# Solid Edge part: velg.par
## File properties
Author: Romil
Template: iso part.par
Last saved by: Romil
Revision: 39
Application: Solid Edge
Material: Aluminum, 1060
Face Style: Aluminum
Fill Style: ANSI38(Aluminum)
Virtual Style: Polished aluminum
Coef. of Thermal Exp: 2.3e-05
Thermal Conductivity: 221.0
Specific Heat: 920.0
Modulus of Elasticity: 68947570000.0
Poisson's Ratio: 0.33
Yield Stress: 27579028.0
Ultimate Stress: 68947570.0
Elongation: 0.0
Density: 2712.000 kg/m^3
Accuracy: 0.990
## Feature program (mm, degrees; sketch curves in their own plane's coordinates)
sketch for "unnamed RevolvedProtrusion 1" plane through (0, 0, 0) normal (0, -1, 0) x-axis (1, 0, 0)
  line (7.5, 13.4) -> (-5.0414, 13.4)
  line (-6.2745, 13.4) -> (-5.0414, 13.4)
  arc centre (-6.2745, 13.5) radius 0.1 from (-6.2745, 13.4) to (-6.3506, 13.4351) cw
  line (-7.5761, 14.872) -> (-6.3506, 13.4351)
  arc centre (-7.5, 14.9369) radius 0.1 from (-7.6, 14.9369) to (-7.5761, 14.872) ccw
  line (-7.6, 18.3) -> (-7.6, 14.9369)
  arc centre (-7.7, 18.3) radius 0.1 from (-7.6, 18.3) to (-7.7, 18.4) ccw
  line (-7.7, 18.4) -> (-9.3, 18.4)
  arc centre (-9.3, 18.3) radius 0.1 from (-9.3, 18.4) to (-9.4, 18.3) ccw
  line (-9.4, 18.3) -> (-9.4, 15)
  arc centre (-9.5, 15) radius 0.1 from (-9.5, 14.9) to (-9.4, 15) ccw
  line (-9.5, 14.9) -> (-11.8, 14.9)
  arc centre (-11.8, 15) radius 0.1 from (-11.8, 14.9) to (-11.9, 15) cw
  line (-11.9, 15.8) -> (-11.9, 15)
  arc centre (-12, 15.8) radius 0.1 from (-12, 15.9) to (-11.9, 15.8) cw
  line (-12, 15.9) -> (-13, 15.9)
  arc centre (-13, 15.8) radius 0.1 from (-13, 15.9) to (-13.1, 15.8) ccw
  line (-13.1, 15.8) -> (-13.1, 14.2)
  line (-11.2018, 14.2) -> (-13.1, 14.2)
  line (-11.2018, 14.2) -> (-7.3, 11.9)
  line (-3.9, 11.9) -> (-7.3, 11.9)
  line (-3.9, 8) -> (-3.9, 11.9)
  line (-3.9, 8) -> (-3.9, 3.6)
  line (-3.9, 3.6) -> (-8.3, 3.6)
  line (-8.3, 3.6) -> (-8.3, 0)
  line (-8.3, 0) -> (0, 0)
  line (0, 0) -> (0, 3.9)
  line (0, 3.9) -> (3.9, 3.9)
  line (3.9, 8) -> (3.9, 3.9)
  line (4.6527, 8) -> (3.9, 8)
  arc centre (4.6527, 8.1) radius 0.1 from (4.6527, 8) to (4.73, 8.0366) ccw
  line (4.73, 8.0366) -> (7.9, 11.9)
  line (8.9, 11.9) -> (7.9, 11.9)
  line (13.1, 12.6985) -> (8.9, 11.9)
  line (13.1, 12.6985) -> (13.1, 13.4)
  line (13.1, 13.4) -> (13.1, 14.8)
  arc centre (13, 14.8) radius 0.1 from (13, 14.9) to (13.1, 14.8) cw
  line (13, 14.9) -> (12, 14.9)
  arc centre (12, 14.8) radius 0.1 from (12, 14.9) to (11.9, 14.8) ccw
  line (11.9, 13.5) -> (11.9, 14.8)
  arc centre (11.8, 13.5) radius 0.1 from (11.8, 13.4) to (11.9, 13.5) ccw
  line (11.8, 13.4) -> (9.5, 13.4)
  arc centre (9.5, 13.5) radius 0.1 from (9.4, 13.5) to (9.5, 13.4) ccw
  line (9.4, 13.5) -> (9.4, 18.3)
  arc centre (9.3, 18.3) radius 0.1 from (9.3, 18.4) to (9.4, 18.3) cw
  line (9.3, 18.4) -> (7.7, 18.4)
  arc centre (7.7, 18.3) radius 0.1 from (7.7, 18.4) to (7.6, 18.3) ccw
  line (7.6, 13.5) -> (7.6, 18.3)
  arc centre (7.5, 13.5) radius 0.1 from (7.5, 13.4) to (7.6, 13.5) ccw
revolve "unnamed RevolvedProtrusion 1" add finite 360 deg
sketch for "unnamed Cutout 1" plane through (0, 0, 0) normal (1, 0, 0) x-axis (0, 1, 0)
  arc centre (0, 0) radius 2.55 from (2.3238, 1.0501) to (0.15, 2.5456) ccw
  line (0.15, 2.5456) -> (0.15, 1.65)
  arc centre (0, 1.65) radius 0.15 from (0.15, 1.65) to (-0.15, 1.65) cw
  line (-0.15, 1.65) -> (-0.15, 2.5456)
  arc centre (0, 0) radius 2.55 from (-0.15, 2.5456) to (-2.3238, 1.0501) ccw
  line (-2.3238, 1.0501) -> (-1.9118, 0.6382)
  arc centre (-2.55, 0) radius 0.9025 from (-1.9118, 0.6382) to (-1.9118, -0.6382) cw
  line (-1.9118, -0.6382) -> (-2.3238, -1.0501)
  arc centre (0, 0) radius 2.55 from (-2.3238, -1.0501) to (-0.15, -2.5456) ccw
  line (-0.15, -2.5456) -> (-0.15, -1.65)
  arc centre (0, -1.65) radius 0.15 from (-0.15, -1.65) to (0.15, -1.65) cw
  line (0.15, -1.65) -> (0.15, -2.5456)
  arc centre (0, 0) radius 2.55 from (0.15, -2.5456) to (2.3238, -1.0501) ccw
  line (2.3238, -1.0501) -> (1.9118, -0.6382)
  arc centre (2.55, 0) radius 0.9025 from (1.9118, -0.6382) to (1.9118, 0.6382) cw
  line (1.9118, 0.6382) -> (2.3238, 1.0501)
extrude "unnamed Cutout 1" cut finite 1471.9732 symmetric
sketch for "ExtrudedCutout_21" plane through (0, 0, 0) normal (1, 0, 0) x-axis (0, 1, 0)
  circle centre (8, 0) radius 2.4
extrude "ExtrudedCutout_21" cut finite 1031.1369 symmetric
sketch for "unnamed Cutout 2" plane through (13.1, 0, 0) normal (1, 0, 0) x-axis (0, 1, 0)
  circle centre (8, 0) radius 3.9
extrude "unnamed Cutout 2" cut to key point along -normal
sketch for "ExtrudedCutout_25" plane through (3.9, 1.95, 0) normal (1, 0, 0) x-axis (0, 1, 0)
  circle centre (6.05, 0) radius 3.1
extrude "ExtrudedCutout_25" cut finite 0.9 along -normal
pattern "unnamed Pattern 1" of "ExtrudedCutout_25", "unnamed Cutout 2", "ExtrudedCutout_21"
extrude "unnamed Cutout 3" cut finite 1031.1369 symmetric
extrude "unnamed Cutout 4" cut finite 9.2
extrude "unnamed Cutout 5" cut finite 0.9
extrude "unnamed Cutout 6" cut finite 1031.1369 symmetric
extrude "unnamed Cutout 7" cut finite 9.2
extrude "unnamed Cutout 8" cut finite 0.9
extrude "unnamed Cutout 9" cut finite 1031.1369 symmetric
extrude "unnamed Cutout 10" cut finite 9.2
extrude "unnamed Cutout 11" cut finite 0.9
extrude "unnamed Cutout 12" cut finite 1031.1369 symmetric
extrude "unnamed Cutout 13" cut finite 9.2
extrude "unnamed Cutout 14" cut finite 0.9
extrude "unnamed Cutout 15" cut finite 1031.1369 symmetric
extrude "unnamed Cutout 16" cut finite 9.2
extrude "unnamed Cutout 17" cut finite 0.9
sketch for "ExtrudedCutout_41" plane through (-3.9, 0, 0) normal (-1, 0, 0) x-axis (0, 0, -1)
  circle centre (0, -8) radius 3.1
extrude "ExtrudedCutout_41" cut finite 0.9 along -normal
pattern "unnamed Pattern 2" of "ExtrudedCutout_41"
extrude "unnamed Cutout 18" cut finite 0.9
extrude "unnamed Cutout 19" cut finite 0.9
extrude "unnamed Cutout 20" cut finite 0.9
extrude "unnamed Cutout 21" cut finite 0.9
extrude "unnamed Cutout 22" cut finite 0.9
sketch for "unnamed Cutout 23" plane through (-13.1, 0, 0) normal (-1, 0, 0) x-axis (0, -1, 0)
extrude "unnamed Cutout 23" cut along -normal
pattern "unnamed Pattern 3" of "unnamed Cutout 23"
extrude "unnamed Cutout 24" cut
extrude "unnamed Cutout 25" cut
extrude "unnamed Cutout 26" cut
extrude "unnamed Cutout 27" cut
extrude "unnamed Cutout 28" cut
Other named dimensions: "Face_Move_2": Distance = 17.3653 mm | "Extend_Surface_1": Distance = 7.3845 mm | "Extend_Surface_2": Distance = 30.3047 mm
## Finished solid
Body 1: sheet body, 1 face, 2 edges, 0 vertices.
  Faces by surface: cone 1
  Edges by curve: circle 2
Body 2: sheet body, 1 face, 2 edges, 0 vertices.
  Faces by surface: cone 1
  Edges by curve: circle 2
Body 3: solid body, 160 faces, 369 edges, 182 vertices.
  Faces by surface: cylinder 86, plane 38, torus 21, cone 15
  Edges by curve: circle 205, line 92, intersection 72
Bounding box of the edges (mm; curved faces can reach further): 40.422 x 64.793 x 64.793, from (-13.1, -32.3966, -32.3966) to (27.3218, 32.3966, 32.3966).
Cylindrical faces by radius (mm): R0.15 x2, R0.5244 x6, R0.525 x12, R0.9025 x2, R2.4 x6, R2.55 x4, R3.1 x12, R3.6 x1, R3.9 x19, R8 x6, R11.2822 x6, R11.9 x2, R13.4 x2, R14.2 x1, R14.9 x2, R15.9 x1, R18.4 x2
Conical faces (half-angle, radius in mm at the cone's reference point): 10.7641 deg R11.9 x1, 30.5179 deg R14.2 x1, 42.5591 deg R8 x8, 49.54 deg R13.4351 x1, 50.6307 deg R8.0366 x6
Toroidal faces (ring radius, tube radius in mm): R8.1 r0.1 x6, R13.5 r0.1 x4, R14.8 r0.1 x2, R14.9369 r0.1 x1, R15 r0.1 x2, R15.8 r0.1 x2, R18.3 r0.1 x4
Planar faces by outward normal: +x 18, +y 2, -x 12, -y 2, oblique 4
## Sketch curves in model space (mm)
arc centre (-13.1, 8.3217, -7.8787) radius 0.525 from (-13.1, 7.809, -7.7659) through (-13.1, 8.086, -8.3478) to (-13.1, 8.6973, -8.2456)
arc centre (-13.1, 4, -6.9282) radius 3.9 from (-13.1, 7.809, -7.7659) through (-13.1, 7.8264, -6.1742) to (-13.1, 7.2064, -4.7081)
arc centre (-13.1, 7.6375, -4.4095) radius 0.5244 from (-13.1, 7.6805, -3.8869) through (-13.1, 7.1834, -4.1473) to (-13.1, 7.2064, -4.7081)
arc centre (-13.1, 8, 0) radius 3.9 from (-13.1, 7.6805, -3.8869) through (-13.1, 9.2602, -3.6908) to (-13.1, 10.63, -2.8798)
arc centre (-13.1, 10.984, -3.2675) radius 0.525 from (-13.1, 11.4895, -3.4093) through (-13.1, 11.2461, -2.8126) to (-13.1, 10.63, -2.8798)
arc centre (-13.1, 0.6266, -0.3618) radius 11.2822 from (-13.1, 11.4895, -3.4093) through (-13.1, 10.3973, -6.0029) to (-13.1, 8.6973, -8.2456)
circle centre (4.6527, 0, 0) radius 8
circle centre (8.9, 0, 0) radius 11.9
arc centre (8.9, 0, 0) radius 11.9 from (8.9, -11.9, 0) through (8.9, -10.3057, 5.95) to (8.9, -5.95, 10.3057)
arc centre (8.9, 0, 0) radius 11.9 from (8.9, -5.95, 10.3057) through (8.9, 0, 11.9) to (8.9, 5.95, 10.3057)
arc centre (8.9, 0, 0) radius 11.9 from (8.9, 5.95, 10.3057) through (8.9, 10.3057, 5.95) to (8.9, 11.9, 0)
arc centre (4.6527, 0, 0) radius 8 from (4.6527, -7.0494, 3.7824) through (4.6527, -6.9282, 4) to (4.6527, -6.8003, 4.2138)
arc centre (4.6527, -4, 6.9282) radius 3.9 from (4.6527, -5.95, 10.3057) through (4.6527, -7.8745, 7.3733) to (4.6527, -6.8265, 4.241)
arc centre (4.6527, -4, 6.9282) radius 3.9 from (4.6527, -0.2596, 8.0324) through (4.6527, -2.6593, 10.5905) to (4.6527, -5.95, 10.3057)
arc centre (4.6527, 0, 0) radius 8 from (4.6527, -6.8003, -4.2138) through (4.6527, -6.9282, -4) to (4.6527, -7.0494, -3.7824)
arc centre (4.6527, -4, -6.9282) radius 3.9 from (4.6527, -0.2491, -7.9961) through (4.6527, -6.2436, -10.1182) to (4.6527, -6.8003, -4.2138)
arc centre (4.6527, 0, 0) radius 8 from (4.6527, 0.2491, -7.9961) through (4.6527, 0, -8) to (4.6527, -0.2491, -7.9961)
arc centre (4.6527, 4, -6.9282) radius 3.9 from (4.6527, 6.8003, -4.2138) through (4.6527, 5.6408, -10.4662) to (4.6527, 0.2491, -7.9961)
arc centre (4.6527, 0, 0) radius 8 from (4.6527, 7.0494, -3.7824) through (4.6527, 6.9282, -4) to (4.6527, 6.8003, -4.2138)
arc centre (4.6527, 8, 0) radius 3.9 from (4.6527, 7.0494, 3.7824) through (4.6527, 11.8844, -0.348) to (4.6527, 7.0494, -3.7824)
arc centre (4.6527, 0, 0) radius 8 from (4.6527, 6.8003, 4.2138) through (4.6527, 6.9282, 4) to (4.6527, 7.0494, 3.7824)
arc centre (4.6527, 0, 0) radius 8 from (4.6527, -0.2491, 7.9961) through (4.6527, 0, 8) to (4.6527, 0.2491, 7.9961)
arc centre (4.6527, 4, 6.9282) radius 3.9 from (4.6527, 0.2491, 7.9961) through (4.6527, 6.2436, 10.1182) to (4.6527, 6.8003, 4.2138)
arc centre (4.6527, -8, 0) radius 3.9 from (4.6527, -11.9, 0) through (4.6527, -10.3227, -3.1329) to (4.6527, -7.086, -3.7914)
arc centre (4.6527, -8, 0) radius 3.9 from (4.6527, -7.086, 3.7914) through (4.6527, -10.5013, 2.9922) to (4.6527, -11.9, 0)
circle centre (-3.9, 8, 0) radius 3.1
circle centre (3.9, 8, 0) radius 3.1
circle centre (13.1, 8, 0) radius 3.9
line (13.1, 0, 13.4) -> (13.1, 0, 14.8)
arc centre (13, 0, 14.8) radius 0.1 from (13, 0, 14.9) through (13.0727, 0, 14.8686) to (13.1, 0, 14.8)
line (13, 0, 14.9) -> (12, 0, 14.9)
arc centre (12, 0, 14.8) radius 0.1 from (12, 0, 14.9) through (11.9273, 0, 14.8686) to (11.9, 0, 14.8)
line (11.9, 0, 13.5) -> (11.9, 0, 14.8)
arc centre (11.8, 0, 13.5) radius 0.1 from (11.8, 0, 13.4) through (11.8727, 0, 13.4314) to (11.9, 0, 13.5)
line (11.8, 0, 13.4) -> (9.5, 0, 13.4)
arc centre (9.5, 0, 13.5) radius 0.1 from (9.4, 0, 13.5) through (9.4314, 0, 13.4273) to (9.5, 0, 13.4)
line (9.4, 0, 13.5) -> (9.4, 0, 18.3)
arc centre (9.3, 0, 18.3) radius 0.1 from (9.3, 0, 18.4) through (9.3727, 0, 18.3686) to (9.4, 0, 18.3)
line (9.3, 0, 18.4) -> (7.7, 0, 18.4)
arc centre (7.7, 0, 18.3) radius 0.1 from (7.7, 0, 18.4) through (7.6273, 0, 18.3686) to (7.6, 0, 18.3)
line (7.6, 0, 13.5) -> (7.6, 0, 18.3)
arc centre (7.5, 0, 13.5) radius 0.1 from (7.5, 0, 13.4) through (7.5727, 0, 13.4314) to (7.6, 0, 13.5)
line (7.5, 0, 13.4) -> (-5.0414, 0, 13.4)
line (-6.2745, 0, 13.4) -> (-5.0414, 0, 13.4)
arc centre (-6.2745, 0, 13.5) radius 0.1 from (-6.2745, 0, 13.4) through (-6.3164, 0, 13.4092) to (-6.3506, 0, 13.4351)
line (-7.5761, 0, 14.872) -> (-6.3506, 0, 13.4351)
arc centre (-7.5, 0, 14.9369) radius 0.1 from (-7.6, 0, 14.9369) through (-7.5938, 0, 14.9023) to (-7.5761, 0, 14.872)
line (-7.6, 0, 18.3) -> (-7.6, 0, 14.9369)
arc centre (-7.7, 0, 18.3) radius 0.1 from (-7.6, 0, 18.3) through (-7.6314, 0, 18.3727) to (-7.7, 0, 18.4)
line (-7.7, 0, 18.4) -> (-9.3, 0, 18.4)
arc centre (-9.3, 0, 18.3) radius 0.1 from (-9.3, 0, 18.4) through (-9.3727, 0, 18.3686) to (-9.4, 0, 18.3)
line (-9.4, 0, 18.3) -> (-9.4, 0, 15)
arc centre (-9.5, 0, 15) radius 0.1 from (-9.5, 0, 14.9) through (-9.4273, 0, 14.9314) to (-9.4, 0, 15)
line (-9.5, 0, 14.9) -> (-11.8, 0, 14.9)
arc centre (-11.8, 0, 15) radius 0.1 from (-11.8, 0, 14.9) through (-11.8727, 0, 14.9314) to (-11.9, 0, 15)
line (-11.9, 0, 15.8) -> (-11.9, 0, 15)
arc centre (-12, 0, 15.8) radius 0.1 from (-12, 0, 15.9) through (-11.9273, 0, 15.8686) to (-11.9, 0, 15.8)
line (-12, 0, 15.9) -> (-13, 0, 15.9)
arc centre (-13, 0, 15.8) radius 0.1 from (-13, 0, 15.9) through (-13.0727, 0, 15.8686) to (-13.1, 0, 15.8)
line (-13.1, 0, 15.8) -> (-13.1, 0, 14.2)
line (-11.2018, 0, 14.2) -> (-13.1, 0, 14.2)
line (-11.2018, 0, 14.2) -> (-7.3, 0, 11.9)
line (-3.9, 0, 11.9) -> (-7.3, 0, 11.9)
line (-3.9, 0, 8) -> (-3.9, 0, 11.9)
line (-3.9, 0, 8) -> (-3.9, 0, 3.6)
line (-3.9, 0, 3.6) -> (-8.3, 0, 3.6)
line (-8.3, 0, 3.6) -> (-8.3, 0, 0)
line (-8.3, 0, 0) -> (0, 0, 0)
line (0, 0, 0) -> (0, 0, 3.9)
line (0, 0, 3.9) -> (3.9, 0, 3.9)
line (3.9, 0, 8) -> (3.9, 0, 3.9)
line (4.6527, 0, 8) -> (3.9, 0, 8)
arc centre (4.6527, 0, 8.1) radius 0.1 from (4.6527, 0, 8) through (4.6955, 0, 8.0096) to (4.73, 0, 8.0366)
line (4.73, 0, 8.0366) -> (7.9, 0, 11.9)
line (8.9, 0, 11.9) -> (7.9, 0, 11.9)
line (13.1, 0, 12.6985) -> (8.9, 0, 11.9)
line (13.1, 0, 12.6985) -> (13.1, 0, 13.4)
arc centre (0, 0, 0) radius 2.55 from (0, 2.3238, 1.0501) through (0, 1.4453, 2.1008) to (0, 0.15, 2.5456)
line (0, 0.15, 2.5456) -> (0, 0.15, 1.65)
arc centre (0, 0, 1.65) radius 0.15 from (0, 0.15, 1.65) through (0, -0.0044, 1.5001) to (0, -0.15, 1.65)
line (0, -0.15, 1.65) -> (0, -0.15, 2.5456)
arc centre (0, 0, 0) radius 2.55 from (0, -0.15, 2.5456) through (0, -1.4453, 2.1008) to (0, -2.3238, 1.0501)
line (0, -2.3238, 1.0501) -> (0, -1.9118, 0.6382)
arc centre (0, -2.55, 0) radius 0.9025 from (0, -1.9118, 0.6382) through (0, -1.6479, -0.0262) to (0, -1.9118, -0.6382)
line (0, -1.9118, -0.6382) -> (0, -2.3238, -1.0501)
arc centre (0, 0, 0) radius 2.55 from (0, -2.3238, -1.0501) through (0, -1.4453, -2.1008) to (0, -0.15, -2.5456)
line (0, -0.15, -2.5456) -> (0, -0.15, -1.65)
arc centre (0, 0, -1.65) radius 0.15 from (0, -0.15, -1.65) through (0, 0.0044, -1.5001) to (0, 0.15, -1.65)
line (0, 0.15, -1.65) -> (0, 0.15, -2.5456)
arc centre (0, 0, 0) radius 2.55 from (0, 0.15, -2.5456) through (0, 1.4453, -2.1008) to (0, 2.3238, -1.0501)
line (0, 2.3238, -1.0501) -> (0, 1.9118, -0.6382)
arc centre (0, 2.55, 0) radius 0.9025 from (0, 1.9118, -0.6382) through (0, 1.6479, 0.0262) to (0, 1.9118, 0.6382)
line (0, 1.9118, 0.6382) -> (0, 2.3238, 1.0501)
circle centre (0, 8, 0) radius 3.1
circle centre (0, 8, 0) radius 2.4
circle centre (0, 0, 0) radius 3.9
circle centre (0, 8, 0) radius 4.1
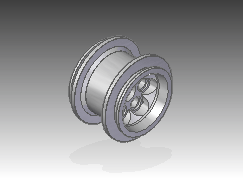
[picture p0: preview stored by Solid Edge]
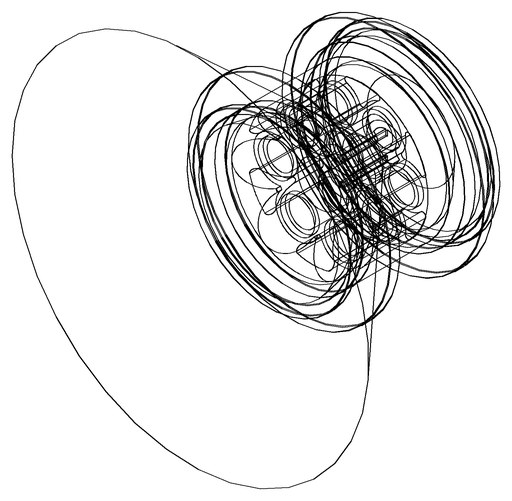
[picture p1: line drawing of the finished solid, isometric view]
